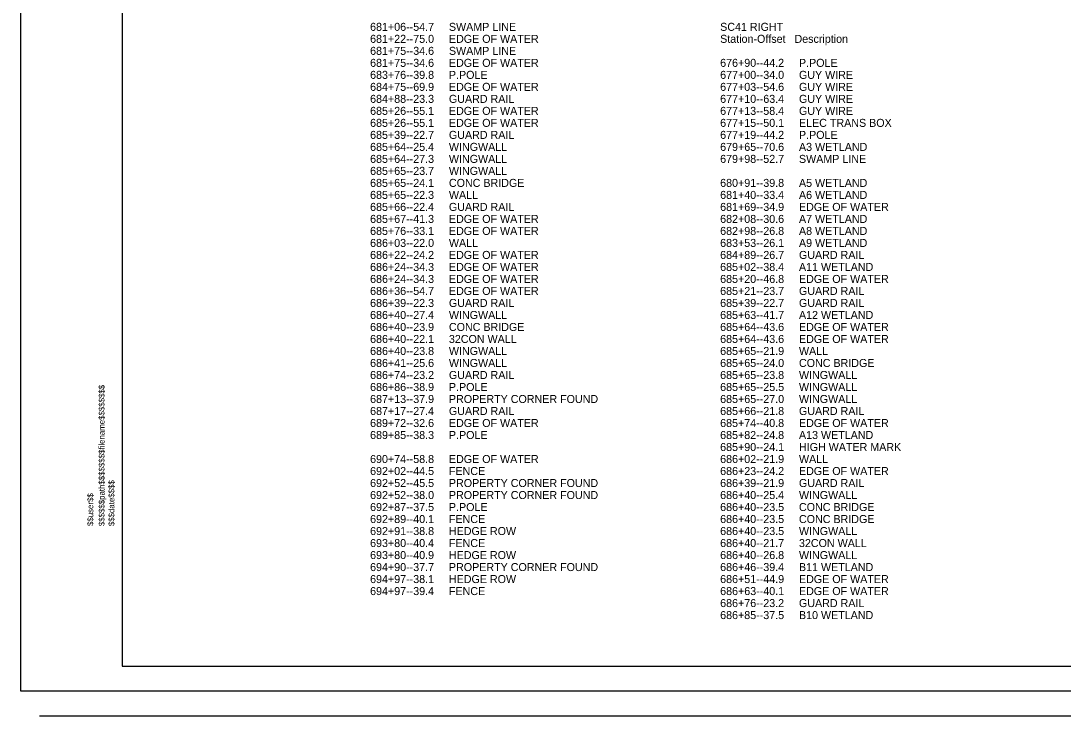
# Model space of a CAD drawing. Extents: x -13615 to 47191, y -1934 to 4415.
# Drawn here: x -10363 to -9321, y 2072 to 2767 of the extents above; entities that cross this region are included whole.
import ezdxf

# ---------------------------------------------------------------- set-up
doc = ezdxf.new("R2010")
doc.units = 0
for name, color, linetype in [('RD_SHT_Bndy', 7, 'Continuous'), ('RD_SHT_ID', 7, 'Continuous'), ('RD_SHT_IplotShp', 7, 'Continuous'), ('RD_SHT_Snap', 7, 'Continuous'), ('RD_TX_StaOff', 7, 'Continuous')]:
    doc.layers.add(name, color=color, linetype=linetype)

msp = doc.modelspace()

# ---------------------------------------------------------------- linework, layer by layer
at = {"layer": 'RD_SHT_Bndy'}
for p, q in [((-10261.5, 3171.6), (-10261.5, 2121.6)), ((-10261.5, 2121.6), (-8586.5, 2121.6)), ((-8584.1, 2096.6), (-10344.1, 2096.6)), ((-8584.1, 2071.6), (-10344.1, 2071.6))]:
    msp.add_line(p, q, dxfattribs=at)
at = {"layer": 'RD_SHT_IplotShp'}
msp.add_lwpolyline([(-10362.7, 3196.6), (-8566.7, 3196.6), (-8566.7, 2096.6), (-10362.7, 2096.6)], close=True, dxfattribs=at)
at = {"layer": 'RD_SHT_Snap'}
msp.add_line((-10362.7, 2096.6), (-10362.7, 3196.6), dxfattribs=at)

# ---------------------------------------------------------------- texts
at = {"layer": 'RD_SHT_ID'}
for s, p in [('$$$$$$path$$$$$$$$filename$$$$$$$$', (-10279, 2261.5)), ('$$$date$$$$', (-10269.2, 2261.5)), ('$$user$$', (-10290.3, 2261.6))]:
    msp.add_text(s, height=5.88, rotation=90, dxfattribs=at).set_placement(p)
at = {"layer": 'RD_TX_StaOff'}
for s, p in [('681+06--54.7     SWAMP LINE', (-10013.5, 2756.6)), ('SC41 RIGHT', (-9663.5, 2756.6)), ('681+22--75.0     EDGE OF WATER', (-10013.5, 2744.6)), ('Station-Offset   Description', (-9663.5, 2744.6)), ('681+75--34.6     SWAMP LINE', (-10013.5, 2732.6)), ('681+75--34.6     EDGE OF WATER', (-10013.5, 2720.6)), ('676+90--44.2     P.POLE', (-9663.5, 2720.6)), ('683+76--39.8     P.POLE', (-10013.5, 2708.6)), ('677+00--34.0     GUY WIRE', (-9663.5, 2708.6)), ('684+75--69.9     EDGE OF WATER', (-10013.5, 2696.6)), ('677+03--54.6     GUY WIRE', (-9663.5, 2696.6)), ('684+88--23.3     GUARD RAIL', (-10013.5, 2684.6)), ('677+10--63.4     GUY WIRE', (-9663.5, 2684.6)), ('685+26--55.1     EDGE OF WATER', (-10013.5, 2672.6)), ('677+13--58.4     GUY WIRE', (-9663.5, 2672.6)), ('685+26--55.1     EDGE OF WATER', (-10013.5, 2660.6)), ('677+15--50.1     ELEC TRANS BOX', (-9663.5, 2660.6)), ('685+39--22.7     GUARD RAIL', (-10013.5, 2648.6)), ('677+19--44.2     P.POLE', (-9663.5, 2648.6)), ('685+64--25.4     WINGWALL', (-10013.5, 2636.6)), ('679+65--70.6     A3 WETLAND', (-9663.5, 2636.6)), ('685+64--27.3     WINGWALL', (-10013.5, 2624.6)), ('679+98--52.7     SWAMP LINE', (-9663.5, 2624.6)), ('685+65--23.7     WINGWALL', (-10013.5, 2612.6)), ('685+65--24.1     CONC BRIDGE', (-10013.5, 2600.6)), ('680+91--39.8     A5 WETLAND', (-9663.5, 2600.6)), ('685+65--22.3     WALL', (-10013.5, 2588.6)), ('681+40--33.4     A6 WETLAND', (-9663.5, 2588.6)), ('685+66--22.4     GUARD RAIL', (-10013.5, 2576.6)), ('681+69--34.9     EDGE OF WATER', (-9663.5, 2576.6)), ('685+67--41.3     EDGE OF WATER', (-10013.5, 2564.6)), ('682+08--30.6     A7 WETLAND', (-9663.5, 2564.6)), ('685+76--33.1     EDGE OF WATER', (-10013.5, 2552.6)), ('682+98--26.8     A8 WETLAND', (-9663.5, 2552.6)), ('686+03--22.0     WALL', (-10013.5, 2540.6)), ('683+53--26.1     A9 WETLAND', (-9663.5, 2540.6)), ('686+22--24.2     EDGE OF WATER', (-10013.5, 2528.6)), ('684+89--26.7     GUARD RAIL', (-9663.5, 2528.6)), ('686+24--34.3     EDGE OF WATER', (-10013.5, 2516.6)), ('685+02--38.4     A11 WETLAND', (-9663.5, 2516.6)), ('686+24--34.3     EDGE OF WATER', (-10013.5, 2504.6)), ('685+20--46.8     EDGE OF WATER', (-9663.5, 2504.6)), ('686+36--54.7     EDGE OF WATER', (-10013.5, 2492.6)), ('685+21--23.7     GUARD RAIL', (-9663.5, 2492.6)), ('686+39--22.3     GUARD RAIL', (-10013.5, 2480.6)), ('685+39--22.7     GUARD RAIL', (-9663.5, 2480.6)), ('686+40--27.4     WINGWALL', (-10013.5, 2468.6)), ('685+63--41.7     A12 WETLAND', (-9663.5, 2468.6)), ('686+40--23.9     CONC BRIDGE', (-10013.5, 2456.6)), ('685+64--43.6     EDGE OF WATER', (-9663.5, 2456.6)), ('686+40--22.1     32CON WALL', (-10013.5, 2444.6)), ('685+64--43.6     EDGE OF WATER', (-9663.5, 2444.6)), ('686+40--23.8     WINGWALL', (-10013.5, 2432.6)), ('685+65--21.9     WALL', (-9663.5, 2432.6)), ('686+41--25.6     WINGWALL', (-10013.5, 2420.6)), ('685+65--24.0     CONC BRIDGE', (-9663.5, 2420.6)), ('686+74--23.2     GUARD RAIL', (-10013.5, 2408.6)), ('685+65--23.8     WINGWALL', (-9663.5, 2408.6)), ('686+86--38.9     P.POLE', (-10013.5, 2396.6)), ('685+65--25.5     WINGWALL', (-9663.5, 2396.6)), ('687+13--37.9     PROPERTY CORNER FOUND', (-10013.5, 2384.6)), ('685+65--27.0     WINGWALL', (-9663.5, 2384.6)), ('687+17--27.4     GUARD RAIL', (-10013.5, 2372.6)), ('685+66--21.8     GUARD RAIL', (-9663.5, 2372.6)), ('689+72--32.6     EDGE OF WATER', (-10013.5, 2360.6)), ('685+74--40.8     EDGE OF WATER', (-9663.5, 2360.6)), ('689+85--38.3     P.POLE', (-10013.5, 2348.6)), ('685+82--24.8     A13 WETLAND', (-9663.5, 2348.6)), ('685+90--24.1     HIGH WATER MARK', (-9663.5, 2336.6)), ('690+74--58.8     EDGE OF WATER', (-10013.5, 2324.6)), ('686+02--21.9     WALL', (-9663.5, 2324.6)), ('692+02--44.5     FENCE', (-10013.5, 2312.6)), ('686+23--24.2     EDGE OF WATER', (-9663.5, 2312.6)), ('692+52--45.5     PROPERTY CORNER FOUND', (-10013.5, 2300.6)), ('686+39--21.9     GUARD RAIL', (-9663.5, 2300.6)), ('692+52--38.0     PROPERTY CORNER FOUND', (-10013.5, 2288.6)), ('686+40--25.4     WINGWALL', (-9663.5, 2288.6)), ('692+87--37.5     P.POLE', (-10013.5, 2276.6)), ('686+40--23.5     CONC BRIDGE', (-9663.5, 2276.6)), ('692+89--40.1     FENCE', (-10013.5, 2264.6)), ('686+40--23.5     CONC BRIDGE', (-9663.5, 2264.6)), ('692+91--38.8     HEDGE ROW', (-10013.5, 2252.6)), ('686+40--23.5     WINGWALL', (-9663.5, 2252.6)), ('693+80--40.4     FENCE', (-10013.5, 2240.6)), ('686+40--21.7     32CON WALL', (-9663.5, 2240.6)), ('693+80--40.9     HEDGE ROW', (-10013.5, 2228.6)), ('686+40--26.8     WINGWALL', (-9663.5, 2228.6)), ('694+90--37.7     PROPERTY CORNER FOUND', (-10013.5, 2216.6)), ('686+46--39.4     B11 WETLAND', (-9663.5, 2216.6)), ('694+97--38.1     HEDGE ROW', (-10013.5, 2204.6)), ('686+51--44.9     EDGE OF WATER', (-9663.5, 2204.6)), ('694+97--39.4     FENCE', (-10013.5, 2192.6)), ('686+63--40.1     EDGE OF WATER', (-9663.5, 2192.6)), ('686+76--23.2     GUARD RAIL', (-9663.5, 2180.6)), ('686+85--37.5     B10 WETLAND', (-9663.5, 2168.6))]:
    msp.add_text(s, height=8, dxfattribs=at).set_placement(p)

doc.saveas('drawing.dxf')
